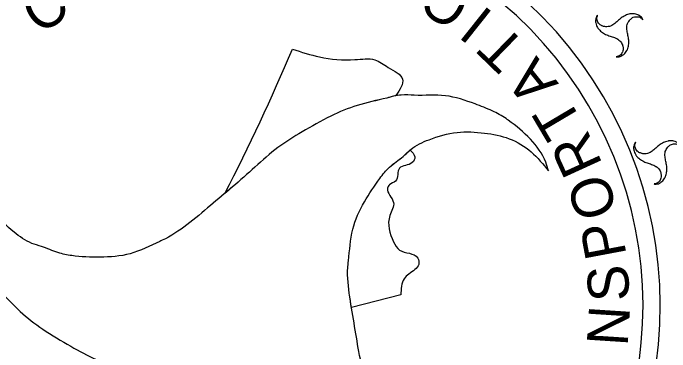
# Model space of a CAD drawing. Extents: x 1376167 to 1379209, y 761324 to 763997.
# Drawn here: x 1377746.7 to 1377830.6, y 763430 to 763473.4 of the extents above; entities that cross this region are included whole.
import ezdxf

# ---------------------------------------------------------------- set-up
doc = ezdxf.new("R2010")
doc.units = 0
doc.layers.add('Sheet Title CELL', color=7, linetype='Continuous')

msp = doc.modelspace()

# ---------------------------------------------------------------- linework, layer by layer
at = {"layer": 'Sheet Title CELL'}
for p, q in [((1377821.37, 763473.099), (1377821.374, 763473.089)), ((1377826.238, 763456.842), (1377826.242, 763456.831)), ((1377773.736, 763450.294), (1377773.736, 763450.294)), ((1377796.238, 763437.31), (1377789.918, 763435.694)), ((1377789.918, 763435.694), (1377789.918, 763435.694))]:
    msp.add_line(p, q, dxfattribs=at)
for centre, radius, start, end in [((1377776.67, 763435.957), 52.717, 61.67024, 241.67024), ((1377776.67, 763435.957), 50.52, 61.67024, 241.67024), ((1377776.67, 763435.957), 52.716, 241.67024, 61.67024), ((1377776.67, 763435.957), 50.52, 241.67024, 61.67024), ((1377526.551, 763577.393), 277.945, 332.78779, 336.9938)]:
    msp.add_arc(centre, radius, start, end, dxfattribs=at)
for points in [[(1377827.175, 763472.498), (1377827.146, 763472.587), (1377826.99, 763472.822), (1377826.763, 763473.017), (1377826.739, 763473.034), (1377826.599, 763473.112), (1377826.422, 763473.183), (1377826.12, 763473.267), (1377825.802, 763473.272), (1377825.668, 763473.275), (1377825.519, 763473.244), (1377825.218, 763473.168), (1377824.948, 763473.059), (1377824.654, 763472.897), (1377824.406, 763472.736), (1377824.172, 763472.538), (1377823.943, 763472.335), (1377823.716, 763472.144), (1377823.476, 763471.946), (1377823.222, 763471.788), (1377823.198, 763471.777), (1377822.894, 763471.651), (1377822.587, 763471.616), (1377822.299, 763471.632), (1377822.157, 763471.662), (1377821.988, 763471.725), (1377821.889, 763471.757), (1377821.709, 763471.871), (1377821.498, 763472.082), (1377821.365, 763472.328), (1377821.289, 763472.575), (1377821.294, 763472.838), (1377821.374, 763473.089), (1377821.37, 763473.099)], [(1377821.374, 763473.089), (1377821.307, 763473.017), (1377821.184, 763472.765), (1377821.129, 763472.471), (1377821.129, 763472.442), (1377821.128, 763472.281), (1377821.155, 763472.095), (1377821.237, 763471.791), (1377821.388, 763471.511), (1377821.455, 763471.395), (1377821.554, 763471.283), (1377821.771, 763471.06), (1377822.001, 763470.88), (1377822.288, 763470.704), (1377822.55, 763470.569), (1377822.839, 763470.469), (1377823.131, 763470.371), (1377823.411, 763470.269), (1377823.698, 763470.161), (1377823.964, 763470.02), (1377823.987, 763470.006), (1377824.244, 763469.806), (1377824.43, 763469.558), (1377824.558, 763469.299), (1377824.607, 763469.16), (1377824.637, 763468.984), (1377824.655, 763468.883), (1377824.65, 763468.668), (1377824.573, 763468.382), (1377824.424, 763468.141), (1377824.249, 763467.951), (1377824.021, 763467.825), (1377823.76, 763467.768)], [(1377823.76, 763467.768), (1377823.858, 763467.749), (1377824.138, 763467.768), (1377824.42, 763467.865), (1377824.442, 763467.88), (1377824.586, 763467.96), (1377824.732, 763468.078), (1377824.957, 763468.3), (1377825.12, 763468.57), (1377825.189, 763468.685), (1377825.237, 763468.833), (1377825.319, 763469.127), (1377825.362, 763469.414), (1377825.37, 763469.753), (1377825.355, 763470.045), (1377825.299, 763470.348), (1377825.235, 763470.649), (1377825.185, 763470.943), (1377825.137, 763471.246), (1377825.124, 763471.547), (1377825.128, 763471.578), (1377825.171, 763471.901), (1377825.292, 763472.182), (1377825.449, 763472.421), (1377825.547, 763472.537), (1377825.687, 763472.645), (1377825.764, 763472.719), (1377825.953, 763472.817), (1377826.238, 763472.892), (1377826.519, 763472.885), (1377826.773, 763472.828), (1377826.997, 763472.693), (1377827.175, 763472.498)], [(1377782.393, 763468.756), (1377785.844, 763467.748), (1377790.363, 763467.406), (1377792.921, 763467.376), (1377794.625, 763466.422), (1377796.46, 763464.918), (1377795.598, 763462.826)], [(1377815.12, 763453.171), (1377814.763, 763454.287), (1377812.812, 763457.22), (1377809.972, 763459.657), (1377809.678, 763459.869), (1377807.919, 763460.853), (1377805.716, 763461.739), (1377801.931, 763462.785), (1377797.955, 763462.851), (1377796.285, 763462.882), (1377794.428, 763462.499), (1377790.665, 763461.545), (1377787.289, 763460.188), (1377783.605, 763458.162), (1377780.516, 763456.153), (1377777.58, 763453.671), (1377774.719, 763451.13), (1377771.891, 763448.75), (1377768.886, 763446.27), (1377765.714, 763444.305), (1377765.409, 763444.167), (1377761.614, 763442.593), (1377757.769, 763442.145), (1377754.168, 763442.347), (1377752.404, 763442.73), (1377750.289, 763443.515), (1377749.05, 763443.916), (1377746.801, 763445.342), (1377744.155, 763447.975), (1377742.495, 763451.054), (1377741.549, 763454.138), (1377741.615, 763457.422), (1377742.613, 763460.558), (1377742.561, 763460.692)], [(1377795.605, 763462.805), (1377794.428, 763462.499), (1377790.665, 763461.545), (1377787.289, 763460.188), (1377783.605, 763458.162), (1377780.516, 763456.153), (1377777.58, 763453.671), (1377774.719, 763451.13), (1377773.736, 763450.294)], [(1377742.613, 763460.558), (1377741.775, 763459.661), (1377740.238, 763456.513), (1377739.551, 763452.836), (1377739.554, 763452.479), (1377739.534, 763450.467), (1377739.875, 763448.135), (1377740.897, 763444.335), (1377742.788, 763440.831), (1377743.625, 763439.386), (1377744.861, 763437.991), (1377747.578, 763435.195), (1377750.453, 763432.953), (1377754.041, 763430.752), (1377757.317, 763429.058), (1377760.92, 763427.807), (1377764.574, 763426.583), (1377768.079, 763425.314), (1377771.666, 763423.966), (1377774.988, 763422.193), (1377775.27, 763422.024), (1377778.485, 763419.527), (1377780.809, 763416.428), (1377782.415, 763413.184), (1377783.026, 763411.452), (1377783.398, 763409.245), (1377783.625, 763407.987), (1377783.563, 763405.304), (1377782.593, 763401.727), (1377780.739, 763398.715), (1377778.554, 763396.342), (1377775.695, 763394.76), (1377772.436, 763394.049)], [(1377772.436, 763394.049), (1377773.659, 763393.816), (1377777.155, 763394.043), (1377780.688, 763395.263), (1377780.967, 763395.45), (1377782.766, 763396.45), (1377784.587, 763397.918), (1377787.399, 763400.698), (1377789.433, 763404.075), (1377790.295, 763405.509), (1377790.904, 763407.364), (1377791.926, 763411.038), (1377792.456, 763414.622), (1377792.559, 763418.862), (1377792.378, 763422.51), (1377791.67, 763426.3), (1377790.877, 763430.065), (1377790.249, 763433.741), (1377789.645, 763437.527), (1377789.489, 763441.286), (1377789.535, 763441.669), (1377790.079, 763445.707), (1377791.586, 763449.226), (1377793.552, 763452.214), (1377794.778, 763453.665), (1377796.518, 763455.017), (1377797.49, 763455.931), (1377799.842, 763457.166), (1377803.415, 763458.097), (1377806.922, 763458.017), (1377810.102, 763457.297), (1377812.902, 763455.61), (1377815.12, 763453.171)], [(1377826.242, 763456.831), (1377826.175, 763456.76), (1377826.052, 763456.508), (1377825.997, 763456.214), (1377825.998, 763456.185), (1377825.996, 763456.024), (1377826.023, 763455.838), (1377826.105, 763455.534), (1377826.256, 763455.253), (1377826.323, 763455.138), (1377826.422, 763455.026), (1377826.64, 763454.802), (1377826.87, 763454.623), (1377827.157, 763454.447), (1377827.419, 763454.311), (1377827.707, 763454.211), (1377827.999, 763454.113), (1377828.28, 763454.012), (1377828.567, 763453.904), (1377828.832, 763453.762), (1377828.855, 763453.749), (1377829.112, 763453.549), (1377829.298, 763453.301), (1377829.427, 763453.041), (1377829.475, 763452.903), (1377829.505, 763452.726), (1377829.523, 763452.626), (1377829.518, 763452.411), (1377829.441, 763452.125), (1377829.292, 763451.884), (1377829.118, 763451.694), (1377828.889, 763451.568), (1377828.628, 763451.511)], [(1377832.043, 763456.24), (1377832.014, 763456.33), (1377831.858, 763456.564), (1377831.631, 763456.759), (1377831.608, 763456.776), (1377831.467, 763456.855), (1377831.291, 763456.926), (1377830.988, 763457.01), (1377830.67, 763457.015), (1377830.536, 763457.017), (1377830.388, 763456.987), (1377830.087, 763456.91), (1377829.816, 763456.802), (1377829.522, 763456.64), (1377829.275, 763456.479), (1377829.04, 763456.28), (1377828.811, 763456.077), (1377828.585, 763455.887), (1377828.344, 763455.688), (1377828.091, 763455.531), (1377828.066, 763455.52), (1377827.762, 763455.394), (1377827.455, 763455.358), (1377827.167, 763455.374), (1377827.026, 763455.405), (1377826.856, 763455.468), (1377826.757, 763455.5), (1377826.577, 763455.614), (1377826.366, 763455.825), (1377826.233, 763456.071), (1377826.157, 763456.318), (1377826.163, 763456.58), (1377826.242, 763456.831), (1377826.238, 763456.842)], [(1377828.628, 763451.511), (1377828.726, 763451.492), (1377829.006, 763451.51), (1377829.288, 763451.608), (1377829.311, 763451.623), (1377829.455, 763451.703), (1377829.6, 763451.82), (1377829.825, 763452.043), (1377829.988, 763452.313), (1377830.057, 763452.428), (1377830.106, 763452.576), (1377830.187, 763452.87), (1377830.23, 763453.157), (1377830.238, 763453.496), (1377830.224, 763453.788), (1377830.167, 763454.091), (1377830.104, 763454.392), (1377830.053, 763454.686), (1377830.005, 763454.989), (1377829.992, 763455.29), (1377829.996, 763455.32), (1377830.04, 763455.643), (1377830.16, 763455.925), (1377830.317, 763456.164), (1377830.416, 763456.28), (1377830.555, 763456.388), (1377830.633, 763456.461), (1377830.821, 763456.56), (1377831.107, 763456.635), (1377831.387, 763456.628), (1377831.642, 763456.571), (1377831.866, 763456.436), (1377832.043, 763456.24)], [(1377789.918, 763435.694), (1377789.645, 763437.527), (1377789.489, 763441.286), (1377789.535, 763441.669), (1377790.079, 763445.707), (1377791.586, 763449.226), (1377793.552, 763452.214), (1377794.778, 763453.665), (1377796.518, 763455.017), (1377797.432, 763455.856)], [(1377797.438, 763455.834), (1377798.02, 763454.971), (1377797.697, 763454.24), (1377796.06, 763453.542), (1377795.555, 763451.88), (1377794.785, 763451.407), (1377794.527, 763450.961), (1377795.302, 763449.14), (1377794.832, 763447.477), (1377795.308, 763444.113), (1377796.073, 763443.062), (1377798.397, 763442.04), (1377798.519, 763441.211), (1377798.023, 763440.555), (1377796.645, 763439.381), (1377796.238, 763437.31)]]:
    msp.add_spline(points, degree=3, dxfattribs=at)

# ---------------------------------------------------------------- texts
for s, height, rotation, p in [('O', 5.237, 146.63035, (1377805.576, 763475.34)), ('C', 5.241, 34.46928, (1377750.071, 763470.472)), ('I', 5.27, 141.49473, (1377808.238, 763473.266)), ('T', 5.25, 135.84482, (1377812.516, 763469.149)), ('A', 5.267, 128.7604, (1377816.471, 763464.336)), ('T', 5.239, 120.67335, (1377819.594, 763459.263)), ('R', 5.265, 114.57357, (1377822.081, 763453.999)), ('O', 5.267, 107.38446, (1377824.02, 763447.948)), ('P', 5.254, 100.69247, (1377825.108, 763442.426)), ('S', 5.234, 93.50062, (1377825.496, 763436.626)), ('N', 5.24, 86.29015, (1377825.222, 763430.685))]:
    msp.add_text(s, height=height, rotation=rotation, dxfattribs=at).set_placement(p)

doc.saveas('drawing.dxf')
